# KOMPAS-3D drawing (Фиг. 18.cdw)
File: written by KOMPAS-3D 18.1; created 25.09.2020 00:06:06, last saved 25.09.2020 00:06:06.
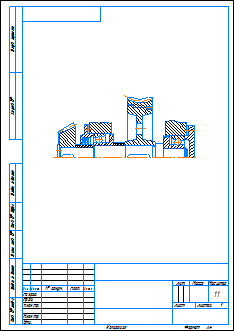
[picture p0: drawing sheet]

Sheet 1: A4, portrait

Document properties: Автор: user; Полное имя файла: C:\Users\user\Desktop\Задания\Фиг. 18.cdw

Title block, sheet 1: scale: 1:1; Количество листов документа: 1; Форматы листов документа: A4

Dimensions and other numbers on the sheet: 1:1; 1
